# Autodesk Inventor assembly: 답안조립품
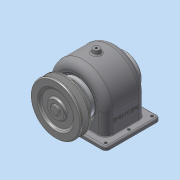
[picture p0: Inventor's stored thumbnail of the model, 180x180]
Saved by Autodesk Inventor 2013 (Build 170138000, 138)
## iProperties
Created: 2015-09
Part Number: 답안조립품
Document SubType Name: Assembly
Designer: Administrator
Author: Administrator
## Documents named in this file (9)
- C:\Users\Administrator\Desktop\450908V1032\답안조립품.iam
- C:\Users\Administrator\Desktop\450908V1032\본체.ipt
- C:\Users\Administrator\Desktop\450908V1032\축.ipt
- C:\Users\Administrator\Desktop\450908V1032\V-벨트풀리.ipt
- C:\Users\Administrator\Desktop\450908V1032\뒤커버.ipt
- C:\Users\Administrator\Desktop\450908V1032\베어링 6203.ipt
- C:\Users\Administrator\Desktop\450908V1032\앞커버.ipt
- C:\Users\Administrator\Desktop\450908V1032\오일 실 17 32 8.ipt
- C:\Users\Administrator\Desktop\450908V1032\스퍼기어.ipt
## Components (1 placed, 1 different names)
1. V-벨트풀리:1
